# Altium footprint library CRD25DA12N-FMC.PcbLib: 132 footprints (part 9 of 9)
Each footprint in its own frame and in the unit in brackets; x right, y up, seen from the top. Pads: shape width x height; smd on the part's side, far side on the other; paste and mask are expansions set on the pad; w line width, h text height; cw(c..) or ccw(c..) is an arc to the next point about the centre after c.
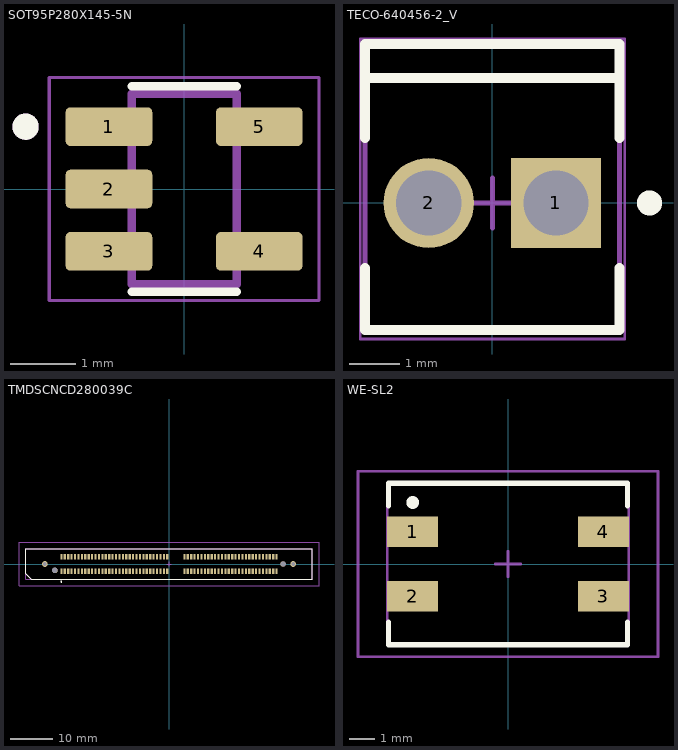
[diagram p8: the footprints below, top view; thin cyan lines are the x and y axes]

## SOT95P280X145-5N [mm]
pads (5):
  rrect25% 1.32x0.59 smd: 1(-1.145,0.95) 2(-1.145,0) 3(-1.145,-0.95) 4(1.145,-0.95) 5(1.145,0.95)
Top Overlay:
  circle w0.2: c-2.415,0.95 r0.1
  lines w0.127: -0.8,-1.565 0.8,-1.565 ; -0.8,1.565 0.8,1.565
Mechanical 13:
  circle w0.2: c-2.415,0.95 r0.1
  lines w0.127: -0.8,-1.45 0.8,-1.45 0.8,1.45 -0.8,1.45 -0.8,-1.45
Mechanical 15:
  lines w0.05: -2.055,-1.7 2.055,-1.7 2.055,1.7 -2.055,1.7 -2.055,-1.7
3D body "SOT-23-5.step": height 1.11, standoff 0.01, extent -1.25,-1.5 1.25,1.5

## TECO-640456-2_V [mm] "HDR, 2-Leads, Body 5.715x5.08mm, Pitch 2.54mm"
height 10.49
pads (2):
  rect 1.8x1.8 hole 1.3: 1(1.27,0)
  round 1.8 hole 1.3: 2(-1.27,0)
Top Overlay:
  circle w0.25: c3.14,0 r0.125
  lines w0.2: -2.54,-1.3 -2.54,-2.54 2.54,-2.54 2.54,-1.3 ; -2.54,1.3 -2.54,3.175 2.54,3.175 2.54,1.3 ; -2.54,2.5 2.54,2.5
Mechanical 13:
  lines w0.1: -2.54,-2.54 -2.54,3.175 2.54,3.175 2.54,-2.54 -2.54,-2.54
Mechanical 15:
  lines w0.05: -2.64,-2.717 2.64,-2.717 2.64,3.275 -2.64,3.275 -2.64,-2.717
  lines w0.1: -0.5,0 0.5,0 ; 0,-0.5 0,0.5
3D body "TE 640456-2 Color.STEP": height 10.09, standoff -3.5, extent -2.54,-2.667 2.54,3.175

## TMDSCNCD280039C [mm]
pads (124):
  rect 0.5x1.2 smd paste+0 mask+0: 1(25.2,1.7) 2(25.2,-1.7) 3(24.4,1.7) 4(24.4,-1.7) 5(23.6,1.7) 6(23.6,-1.7) 7(22.8,1.7) 8(22.8,-1.7) 9(22,1.7) 10(22,-1.7) 11(21.2,1.7) 12(21.2,-1.7) 13(20.4,1.7) 14(20.4,-1.7) 15(19.6,1.7) 16(19.6,-1.7) 17(18.8,1.7) 18(18.8,-1.7) 19(18,1.7) 20(18,-1.7) 21(17.2,1.7) 22(17.2,-1.7) 23(16.4,1.7) 24(16.4,-1.7) 25(15.6,1.7) 26(15.6,-1.7) 27(14.8,1.7) 28(14.8,-1.7) 29(14,1.7) 30(14,-1.7) 31(13.2,1.7) 32(13.2,-1.7) 33(12.4,1.7) 34(12.4,-1.7) 35(11.6,1.7) 36(11.6,-1.7) 37(10.8,1.7) 38(10.8,-1.7) 39(10,1.7) 40(10,-1.7) 41(9.2,1.7) 42(9.2,-1.7) 43(8.4,1.7) 44(8.4,-1.7) 45(7.6,1.7) 46(7.6,-1.7) 47(6.8,1.7) 48(6.8,-1.7) 49(6,1.7) 50(6,-1.7) 51(5.2,1.7) 52(5.2,-1.7) 53(4.4,1.7) 54(4.4,-1.7) 55(3.6,1.7) 56(3.6,-1.7) 57(-0.4,1.7) 58(-0.4,-1.7) 59(-1.2,1.7) 60(-1.2,-1.7) 61(-2,1.7) 62(-2,-1.7) 63(-2.8,1.7) 64(-2.8,-1.7) 65(-3.6,1.7) 66(-3.6,-1.7) 67(-4.4,1.7) 68(-4.4,-1.7) 69(-5.2,1.7) 70(-5.2,-1.7) 71(-6,1.7) 72(-6,-1.7) 73(-6.8,1.7) 74(-6.8,-1.7) 75(-7.6,1.7) 76(-7.6,-1.7) 77(-8.4,1.7) 78(-8.4,-1.7) 79(-9.2,1.7) 80(-9.2,-1.7) 81(-10,1.7) 82(-10,-1.7) 83(-10.8,1.7) 84(-10.8,-1.7) 85(-11.6,1.7) 86(-11.6,-1.7) 87(-12.4,1.7) 88(-12.4,-1.7) 89(-13.2,1.7) 90(-13.2,-1.7) 91(-14,1.7) 92(-14,-1.7) 93(-14.8,1.7) 94(-14.8,-1.7) 95(-15.6,1.7) 96(-15.6,-1.7) 97(-16.4,1.7) 98(-16.4,-1.7) 99(-17.2,1.7) 100(-17.2,-1.7) 101(-18,1.7) 102(-18,-1.7) 103(-18.8,1.7) 104(-18.8,-1.7) 105(-19.6,1.7) 106(-19.6,-1.7) 107(-20.4,1.7) 108(-20.4,-1.7) 109(-21.2,1.7) 110(-21.2,-1.7) 111(-22,1.7) 112(-22,-1.7) 113(-22.8,1.7) 114(-22.8,-1.7) 115(-23.6,1.7) 116(-23.6,-1.7) 117(-24.4,1.7) 118(-24.4,-1.7) 119(-25.2,1.7) 120(-25.2,-1.7)
  round 1.34 hole 0.84 paste-1000 mask+0: 121(-29.05,0) 122(29.05,0)
  round 1.27 hole 1.27 unplated paste-1000 mask+0: ""(-26.7,-1.5) ""(26.7,0)
Top Overlay:
  circle w0.25: c-25.2,-4.125 r0.125
  lines w0.2: -33.55,-2.295 -33.55,3.565 33.55,3.565 33.55,-3.565 -32.28,-3.565 -33.55,-2.295
Top Paste:
  circle w1.27: c-29.05,0 r0.635
  circle w1.27: c29.05,0 r0.635
Mechanical 5:
  lines w0.2: -35.115,-5.09 35.115,-5.09 35.115,5.09 -35.115,5.09 -35.115,-5.09
  text ".Designator" at 0,0.188 h1
Mechanical 13:
  lines w0.2: -33.55,-3.565 33.55,-3.565 33.55,3.565 -33.55,3.565 -33.55,-3.565
Mechanical 15:
  lines w0.2: -35.115,-5.09 35.115,-5.09 35.115,5.09 -35.115,5.09 -35.115,-5.09
Mechanical 16:
  lines w0.1: -0.5,0 0.5,0 ; 0,-0.5 0,0.5
3D body "TI TMS320F280039C.step": height 57.35, standoff 2, extent -33.874,-4.89 34.671,5.68
3D body "Samtec HSEC8-160-01-L-DV-A-BL.stp": height 12.4, standoff -1.3, extent -33.525,-3.5 33.525,3.5

## WE-SL2 [mm] "SMD Inductor, 4-Leads, Body 6.3 x 9.5 mm"
height 5.3
pads (4):
  rect 2x1.2 smd: 1(-3.75,1.27) 2(-3.75,-1.27) 3(3.75,-1.27) 4(3.75,1.27)
Top Overlay:
  circle w0.25: c-3.75,2.42 r0.125
  lines w0.2: -4.699,-2.286 -4.699,-3.175 ; -4.699,2.286 -4.699,3.175 4.699,3.175 4.699,2.286 ; 4.699,-2.286 4.699,-3.175 ; -4.699,-3.175 4.699,-3.175 ; -4.699,-3.175 4.699,-3.175 ; -4.699,-3.175 4.699,-3.175
Mechanical 13:
  lines w0.1: -4.75,-3.15 4.75,-3.15 4.75,3.15 -4.75,3.15 -4.75,-3.15
Mechanical 15:
  lines w0.1: -0.5,0 0.5,0 ; 0,-0.5 0,0.5 ; -5.9,-3.65 5.9,-3.65 5.9,3.65 -5.9,3.65 -5.9,-3.65
3D body "744229.stp": height 5, standoff 0, extent -4.6,-3 4.6,3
